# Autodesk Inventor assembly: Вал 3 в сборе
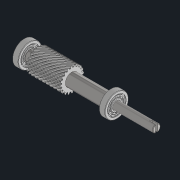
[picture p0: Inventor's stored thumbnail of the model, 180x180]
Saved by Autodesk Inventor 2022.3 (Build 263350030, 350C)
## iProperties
Created: 2022-08
Part Number: Вал 3 в сборе
Document SubType Name: Assembly
Designer: Карташов
Author: Карташов
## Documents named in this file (5)
- C:\Users\wsr\Desktop\Новая папка\10. Редуктор\Вал 3 в сборе.iam
- C:\Users\wsr\Desktop\Новая папка\10. Редуктор\Вал 3.ipt
- C:\Users\wsr\Desktop\Новая папка\10. Редуктор\GIVEN\ISO 15 - 30 x 90 x 23.ipt
- C:\Users\wsr\Desktop\Новая папка\10. Редуктор\GIVEN\Стопорное кольцо DIN 471 - 40 x 2.5.ipt
- C:\Users\wsr\Desktop\Новая папка\10. Редуктор\GIVEN\Червяк 1.ipt
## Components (5 placed, 4 different names)
1. Вал 3:1 — Совмещение:1, Совмещение:2, Совмещение:3, С поворотом:1, С поворотом:2, С поворотом:3
2. ISO 15 - 30 x 90 x 23:1 — С поворотом:1
3. Стопорное кольцо DIN 471 - 40 x 2.5:1 — С поворотом:2
4. Червяк 1:1 — Совмещение:1, Совмещение:2, Совмещение:3
5. ISO 15 - 30 x 90 x 23:2 — С поворотом:3
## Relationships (6: Mate 3, RevoluteJoint 3)
- Совмещение:1 [Mate]: Вал 3:1 ↔ Червяк 1:1
- Совмещение:2 [Mate]: Вал 3:1 ↔ Червяк 1:1
- Совмещение:3 [Mate]: Вал 3:1 ↔ Червяк 1:1
- С поворотом:1 [RevoluteJoint]: Вал 3:1 ↔ ISO 15 - 30 x 90 x 23:1
- С поворотом:2 [RevoluteJoint]: Вал 3:1 ↔ Стопорное кольцо DIN 471 - 40 x 2.5:1
- С поворотом:3 [RevoluteJoint]: Вал 3:1 ↔ ISO 15 - 30 x 90 x 23:2
